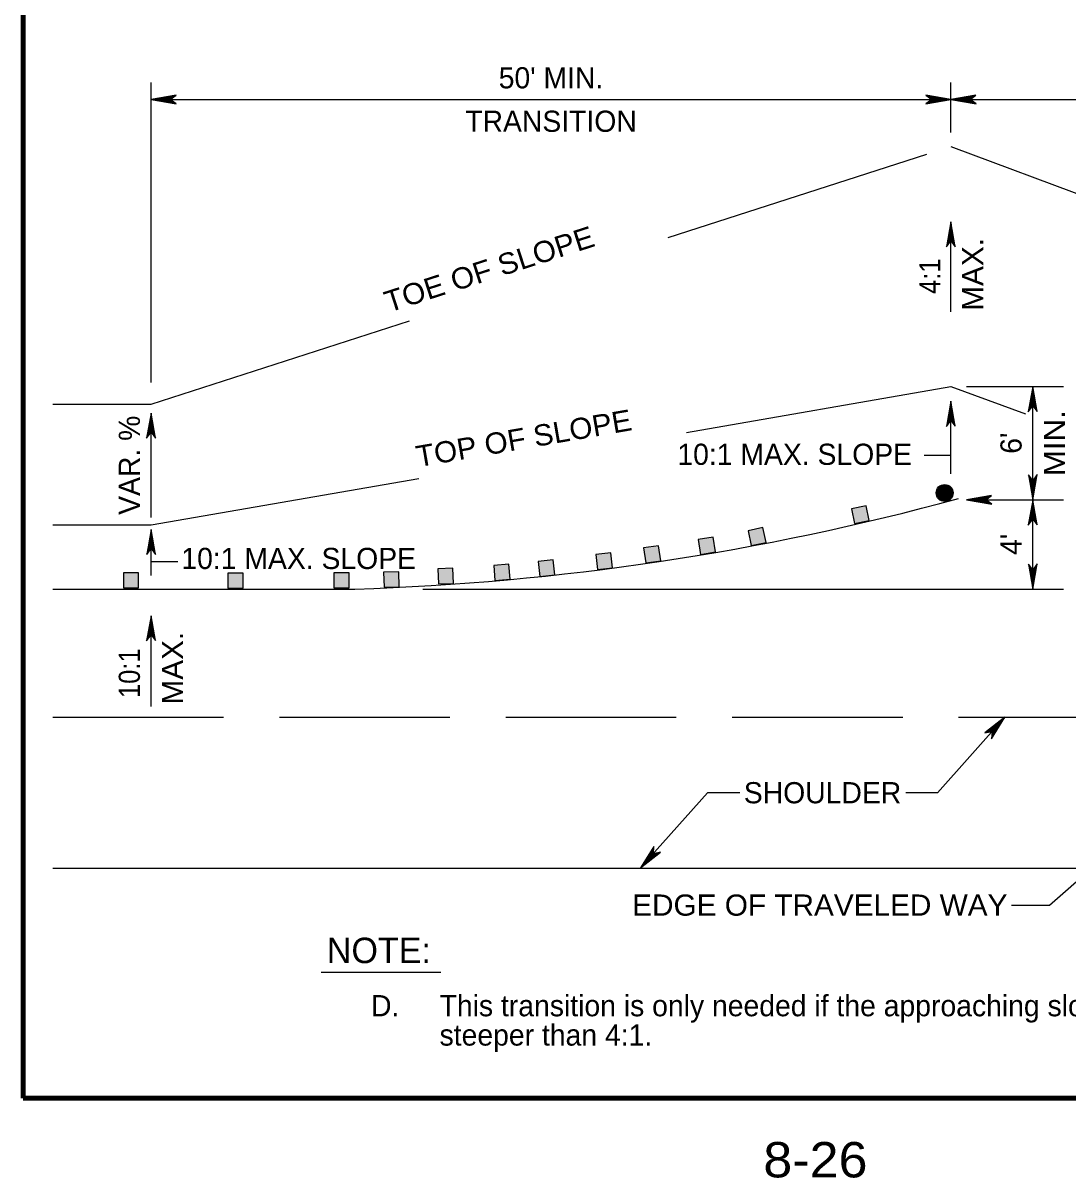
# Model space of a CAD drawing. Extents: x 11.149 to 11.823, y 1.038 to 1.922.
# Drawn here: x 11.1943 to 11.5789, y 1.0551 to 1.4804 of the extents above; entities that cross this region are included whole.
import ezdxf
from ezdxf.enums import TextEntityAlignment as Align

# ---------------------------------------------------------------- set-up
doc = ezdxf.new("R2010")
doc.units = 0
doc.header["$LTSCALE"] = 0.0031
doc.linetypes.add('LONG_DASHED', pattern=[7.5, 6, -1.5])
for name, color, linetype, lineweight in [('1', 7, 'Continuous', 90), ('21', 7, 'Continuous', 25), ('24', 7, 'Continuous', 25), ('5', 7, 'LONG_DASHED', 25), ('60', 7, 'Continuous', 25)]:
    doc.layers.add(name, color=color, linetype=linetype, lineweight=lineweight)

msp = doc.modelspace()

# ---------------------------------------------------------------- hatches: boundary and pattern name
at = {"layer": '60'}
for points in [[(11.499225, 1.301517), (11.500383, 1.296083), (11.505817, 1.297233), (11.504658, 1.302667)], [(11.461208, 1.29345), (11.462367, 1.288017), (11.4678, 1.289175), (11.466642, 1.294608)], [(11.442808, 1.290225), (11.443717, 1.284742), (11.4492, 1.28565), (11.448292, 1.291133)], [(11.405167, 1.2847), (11.4058, 1.279183), (11.411325, 1.279817), (11.410692, 1.285333)], [(11.422742, 1.2871), (11.423517, 1.281592), (11.429017, 1.282367), (11.428242, 1.287867)], [(11.367575, 1.28065), (11.368025, 1.275117), (11.373558, 1.275558), (11.373117, 1.2811)], [(11.383892, 1.282125), (11.384475, 1.2766), (11.39, 1.277175), (11.389417, 1.2827)], [(11.231217, 1.278008), (11.231217, 1.27245), (11.236775, 1.27245), (11.236775, 1.278008)], [(11.269733, 1.277842), (11.269733, 1.272283), (11.275292, 1.272283), (11.275292, 1.277842)], [(11.308758, 1.278008), (11.308758, 1.27245), (11.314317, 1.27245), (11.314317, 1.278008)], [(11.327033, 1.278175), (11.327233, 1.272617), (11.332783, 1.272817), (11.332592, 1.278367)], [(11.346983, 1.279408), (11.347175, 1.273858), (11.352725, 1.27405), (11.352533, 1.279608)]]:
    msp.add_hatch(color=256, dxfattribs=at).paths.add_polyline_path(points)

# ---------------------------------------------------------------- linework, layer by layer
at = {"layer": '1'}
for q in [(11.194317, 1.876217), (11.77765, 1.08455)]:
    msp.add_line((11.194317, 1.08455), q, dxfattribs=at)
at = {"layer": '21'}
for radius in [0.003125, 0.002917, 0.002708, 0.0025, 0.002292, 0.002083, 0.001875, 0.001667, 0.001458, 0.00125, 0.001042, 0.000833, 0.000625, 0.000417, 0.000208]:
    msp.add_circle((11.533558, 1.307351), radius, dxfattribs=at)
at = {"layer": '24'}
for p, q in [((11.241425, 1.348025), (11.241425, 1.458475)), ((11.535867, 1.440125), (11.535867, 1.458475)), ((11.241425, 1.452242), (11.535867, 1.452242)), ((11.535867, 1.452242), (11.599908, 1.452242)), ((11.535867, 1.374), (11.535867, 1.407233)), ((11.541658, 1.346508), (11.577317, 1.346508)), ((11.535867, 1.31445), (11.535867, 1.341108)), ((11.241425, 1.29835), (11.241425, 1.336775)), ((11.53555, 1.321183), (11.525975, 1.321183)), ((11.541658, 1.304875), (11.577317, 1.304875)), ((11.241442, 1.276975), (11.241442, 1.293942)), ((11.251242, 1.28205), (11.241442, 1.28205)), ((11.205308, 1.271983), (11.316425, 1.271983)), ((11.341458, 1.271983), (11.577317, 1.271983)), ((11.241425, 1.228758), (11.241425, 1.262167)), ((11.205308, 1.224767), (11.268108, 1.224767)), ((11.288642, 1.224767), (11.351442, 1.224767)), ((11.371975, 1.224767), (11.434775, 1.224767)), ((11.455308, 1.224767), (11.518108, 1.224767)), ((11.530925, 1.196983), (11.555683, 1.224817)), ((11.538642, 1.224767), (11.601442, 1.224767)), ((11.446283, 1.196983), (11.421642, 1.169275)), ((11.458183, 1.196983), (11.446283, 1.196983)), ((11.530925, 1.196983), (11.519217, 1.196983)), ((11.205308, 1.169208), (11.768167, 1.169208)), ((11.304008, 1.130908), (11.34815, 1.130908))]:
    msp.add_line(p, q, dxfattribs=at)
for points in [[(11.241425, 1.452242), (11.250658, 1.450608), (11.248458, 1.452242), (11.250617, 1.45385), (11.241425, 1.452242), (11.242033, 1.452258), (11.2504, 1.450733), (11.248283, 1.452267), (11.250242, 1.453725), (11.242367, 1.452292), (11.242675, 1.452242), (11.249842, 1.450967), (11.248233, 1.452258), (11.249892, 1.453517), (11.242817, 1.452242), (11.243125, 1.452292), (11.249392, 1.451158), (11.248167, 1.452242), (11.249417, 1.453367), (11.244017, 1.452292), (11.244533, 1.452292), (11.248925, 1.451392), (11.248067, 1.452217), (11.248992, 1.453133), (11.244625, 1.452242), (11.245125, 1.452217), (11.248425, 1.45165), (11.247783, 1.452292), (11.248475, 1.452925), (11.245575, 1.452242), (11.246042, 1.4522), (11.248025, 1.451817), (11.247692, 1.452267), (11.248233, 1.452758), (11.246283, 1.452242), (11.247575, 1.451933), (11.247392, 1.452292), (11.247958, 1.452642), (11.246608, 1.452292), (11.247458, 1.452075), (11.2471, 1.452358), (11.247508, 1.452525), (11.2471, 1.452267), (11.247317, 1.452217)], [(11.535867, 1.452242), (11.526625, 1.453875), (11.528833, 1.452242), (11.526675, 1.450633), (11.535867, 1.452242), (11.53525, 1.452225), (11.526883, 1.453758), (11.529008, 1.452225), (11.52705, 1.450758), (11.534917, 1.4522), (11.534617, 1.452242), (11.527442, 1.453517), (11.52905, 1.452225), (11.5274, 1.450967), (11.534475, 1.452242), (11.534167, 1.4522), (11.5279, 1.453325), (11.529117, 1.452242), (11.527875, 1.451117), (11.533275, 1.4522), (11.53275, 1.4522), (11.528367, 1.453092), (11.529217, 1.452267), (11.5283, 1.45135), (11.532658, 1.452242), (11.532167, 1.452275), (11.528867, 1.452833), (11.5295, 1.452192), (11.528817, 1.451567), (11.531708, 1.452242), (11.53125, 1.452292), (11.529267, 1.452667), (11.529592, 1.452225), (11.52905, 1.451733), (11.531008, 1.452242), (11.529717, 1.45255), (11.5299, 1.4522), (11.529333, 1.451842), (11.530683, 1.452192), (11.529833, 1.452408), (11.530183, 1.452125), (11.529783, 1.451958), (11.530183, 1.452225), (11.529975, 1.452267)], [(11.535867, 1.452242), (11.545108, 1.450608), (11.5429, 1.452242), (11.545058, 1.45385), (11.535867, 1.452242), (11.536483, 1.452258), (11.54485, 1.450733), (11.542725, 1.452267), (11.544683, 1.453725), (11.536808, 1.452292), (11.537117, 1.452242), (11.544283, 1.450967), (11.542675, 1.452258), (11.544333, 1.453517), (11.537258, 1.452242), (11.537567, 1.452292), (11.543833, 1.451158), (11.542617, 1.452242), (11.543858, 1.453367), (11.538458, 1.452292), (11.538983, 1.452292), (11.543367, 1.451392), (11.542517, 1.452217), (11.543433, 1.453133), (11.539075, 1.452242), (11.539567, 1.452217), (11.542867, 1.45165), (11.542233, 1.452292), (11.542917, 1.452925), (11.540017, 1.452242), (11.540483, 1.4522), (11.542467, 1.451817), (11.542142, 1.452267), (11.542683, 1.452758), (11.540725, 1.452242), (11.542017, 1.451933), (11.541833, 1.452292), (11.5424, 1.452642), (11.54105, 1.452292), (11.5419, 1.452075), (11.541542, 1.452358), (11.54195, 1.452525), (11.541542, 1.452267), (11.541758, 1.452217)], [(11.535867, 1.407233), (11.534233, 1.397992), (11.535867, 1.4002), (11.537475, 1.398042), (11.535867, 1.407233), (11.535883, 1.406617), (11.53435, 1.39825), (11.535883, 1.400375), (11.53735, 1.398417), (11.535908, 1.406292), (11.535867, 1.405983), (11.534592, 1.398808), (11.535883, 1.400417), (11.537142, 1.398767), (11.535867, 1.405842), (11.535908, 1.405533), (11.534783, 1.399267), (11.535867, 1.400483), (11.536992, 1.399242), (11.535908, 1.404642), (11.535908, 1.404117), (11.535017, 1.399733), (11.535842, 1.400583), (11.536758, 1.399667), (11.535867, 1.404025), (11.535833, 1.403533), (11.535275, 1.400233), (11.535917, 1.400867), (11.536542, 1.400183), (11.535867, 1.403075), (11.535817, 1.402617), (11.535442, 1.400633), (11.535883, 1.400958), (11.536375, 1.400417), (11.535867, 1.402375), (11.535558, 1.401083), (11.535908, 1.401267), (11.536267, 1.4007), (11.535917, 1.40205), (11.5357, 1.4012), (11.535983, 1.401558), (11.53615, 1.40115), (11.535883, 1.40155), (11.535842, 1.401342)], [(11.565983, 1.346508), (11.56435, 1.337267), (11.565983, 1.339475), (11.567592, 1.337317), (11.565983, 1.346508), (11.566, 1.345892), (11.564475, 1.337525), (11.566008, 1.33965), (11.567467, 1.337692), (11.566033, 1.345558), (11.565983, 1.34525), (11.564708, 1.338083), (11.566008, 1.339692), (11.567258, 1.338042), (11.565983, 1.345117), (11.566033, 1.344808), (11.5649, 1.338542), (11.565983, 1.339758), (11.567117, 1.338517), (11.566033, 1.343917), (11.566033, 1.343392), (11.565133, 1.339008), (11.565958, 1.339858), (11.566875, 1.338942), (11.565983, 1.3433), (11.565958, 1.342808), (11.565392, 1.339508), (11.566033, 1.340142), (11.566667, 1.339458), (11.565983, 1.34235), (11.565942, 1.341883), (11.565558, 1.339908), (11.566008, 1.340233), (11.5665, 1.339692), (11.565983, 1.34165), (11.565675, 1.340358), (11.566033, 1.340542), (11.566383, 1.339975), (11.566033, 1.341325), (11.565817, 1.340475), (11.5661, 1.340825), (11.566267, 1.340425), (11.566008, 1.340825), (11.565958, 1.340617)], [(11.565983, 1.271983), (11.565983, 1.304875), (11.565983, 1.346508)], [(11.535867, 1.341108), (11.534233, 1.331867), (11.535867, 1.334075), (11.537475, 1.331917), (11.535867, 1.341108), (11.535883, 1.340492), (11.53435, 1.332125), (11.535883, 1.334242), (11.53735, 1.332283), (11.535908, 1.340158), (11.535867, 1.33985), (11.534592, 1.332683), (11.535883, 1.334292), (11.537142, 1.332642), (11.535867, 1.339708), (11.535908, 1.339408), (11.534783, 1.333142), (11.535867, 1.334358), (11.536992, 1.333117), (11.535908, 1.338517), (11.535908, 1.337992), (11.535017, 1.333608), (11.535842, 1.334458), (11.536758, 1.333542), (11.535867, 1.3379), (11.535833, 1.337408), (11.535275, 1.334108), (11.535917, 1.334742), (11.536542, 1.33405), (11.535867, 1.33695), (11.535817, 1.336483), (11.535442, 1.334508), (11.535883, 1.334833), (11.536375, 1.334292), (11.535867, 1.336242), (11.535558, 1.33495), (11.535908, 1.335142), (11.536267, 1.334575), (11.535917, 1.335917), (11.5357, 1.335075), (11.535983, 1.335425), (11.53615, 1.335017), (11.535883, 1.335425), (11.535842, 1.335217)], [(11.535867, 1.341108), (11.534233, 1.331867), (11.535867, 1.334075), (11.537475, 1.331917), (11.535867, 1.341108), (11.535883, 1.340492), (11.53435, 1.332125), (11.535883, 1.334242), (11.53735, 1.332283), (11.535908, 1.340158), (11.535867, 1.33985), (11.534592, 1.332683), (11.535883, 1.334292), (11.537142, 1.332642), (11.535867, 1.339708), (11.535908, 1.339408), (11.534783, 1.333142), (11.535867, 1.334358), (11.536992, 1.333117), (11.535908, 1.338517), (11.535908, 1.337992), (11.535017, 1.333608), (11.535842, 1.334458), (11.536758, 1.333542), (11.535867, 1.3379), (11.535833, 1.337408), (11.535275, 1.334108), (11.535917, 1.334742), (11.536542, 1.33405), (11.535867, 1.33695), (11.535817, 1.336483), (11.535442, 1.334508), (11.535883, 1.334833), (11.536375, 1.334292), (11.535867, 1.336242), (11.535558, 1.33495), (11.535908, 1.335142), (11.536267, 1.334575), (11.535917, 1.335917), (11.5357, 1.335075), (11.535983, 1.335425), (11.53615, 1.335017), (11.535883, 1.335425), (11.535842, 1.335217)], [(11.241425, 1.336775), (11.239792, 1.327533), (11.241425, 1.329742), (11.243033, 1.327583), (11.241425, 1.336775), (11.241442, 1.336167), (11.239908, 1.3278), (11.241442, 1.329917), (11.2429, 1.327958), (11.241467, 1.335833), (11.241425, 1.335525), (11.24015, 1.328358), (11.241442, 1.329967), (11.242692, 1.328308), (11.241425, 1.335383), (11.241467, 1.335075), (11.240333, 1.328808), (11.241425, 1.330033), (11.24255, 1.328783), (11.241467, 1.334183), (11.241467, 1.333667), (11.240567, 1.329275), (11.241392, 1.330133), (11.242317, 1.329208), (11.241425, 1.333567), (11.241392, 1.333075), (11.240825, 1.329775), (11.241467, 1.330408), (11.2421, 1.329725), (11.241425, 1.332625), (11.241375, 1.332158), (11.241, 1.330175), (11.241442, 1.3305), (11.241933, 1.329967), (11.241417, 1.331917), (11.241117, 1.330625), (11.241467, 1.330808), (11.241825, 1.330242), (11.241467, 1.331592), (11.241258, 1.330742), (11.241533, 1.3311), (11.2417, 1.330692), (11.241442, 1.3311), (11.241392, 1.330883)], [(11.565983, 1.304875), (11.567617, 1.314117), (11.565983, 1.311908), (11.564375, 1.314067), (11.565983, 1.304875), (11.565967, 1.305492), (11.5675, 1.313858), (11.565967, 1.311742), (11.564508, 1.3137), (11.565942, 1.305825), (11.565983, 1.306133), (11.567258, 1.3133), (11.565967, 1.311692), (11.564717, 1.313342), (11.565983, 1.306275), (11.565942, 1.306575), (11.567075, 1.312842), (11.565983, 1.311625), (11.564858, 1.312867), (11.565942, 1.307467), (11.565942, 1.307992), (11.566842, 1.312375), (11.566008, 1.311525), (11.565092, 1.312442), (11.565983, 1.308083), (11.566017, 1.308575), (11.566583, 1.311875), (11.565942, 1.311242), (11.565308, 1.311933), (11.565983, 1.309033), (11.566033, 1.3095), (11.566408, 1.311475), (11.565967, 1.31115), (11.565475, 1.311692), (11.565983, 1.309742), (11.566292, 1.311033), (11.565942, 1.310842), (11.565583, 1.311408), (11.565942, 1.310067), (11.56615, 1.310908), (11.565875, 1.310558), (11.565708, 1.310967), (11.565967, 1.310558), (11.566008, 1.310767)], [(11.541658, 1.304875), (11.5509, 1.303242), (11.548692, 1.304875), (11.55085, 1.306483), (11.541658, 1.304875), (11.542267, 1.304892), (11.550633, 1.303367), (11.548517, 1.3049), (11.550475, 1.306358), (11.5426, 1.304925), (11.542908, 1.304875), (11.550075, 1.3036), (11.548467, 1.3049), (11.550125, 1.30615), (11.54305, 1.304875), (11.543358, 1.304925), (11.549625, 1.303792), (11.5484, 1.304875), (11.54965, 1.306008), (11.54425, 1.304925), (11.544767, 1.304925), (11.549158, 1.304025), (11.5483, 1.30485), (11.549225, 1.305767), (11.544867, 1.304875), (11.545358, 1.30485), (11.548658, 1.304283), (11.548025, 1.304925), (11.548708, 1.305558), (11.545808, 1.304875), (11.546275, 1.304833), (11.548258, 1.30445), (11.547933, 1.3049), (11.548467, 1.305392), (11.546517, 1.304875), (11.547808, 1.304567), (11.547625, 1.304925), (11.548192, 1.305275), (11.546842, 1.304925), (11.547692, 1.304708), (11.547333, 1.304992), (11.547742, 1.305158), (11.547333, 1.3049), (11.54755, 1.30485)], [(11.565983, 1.304767), (11.56435, 1.295525), (11.565983, 1.297733), (11.567592, 1.295575), (11.565983, 1.304767), (11.566, 1.30415), (11.564475, 1.295783), (11.566008, 1.2979), (11.567467, 1.295942), (11.566033, 1.303817), (11.565983, 1.303508), (11.564708, 1.296342), (11.566008, 1.29795), (11.567258, 1.2963), (11.565983, 1.303367), (11.566033, 1.303067), (11.5649, 1.2968), (11.565983, 1.298017), (11.567117, 1.296775), (11.566033, 1.302167), (11.566033, 1.30165), (11.565133, 1.297258), (11.565958, 1.298117), (11.566875, 1.2972), (11.565983, 1.301558), (11.565958, 1.301067), (11.565392, 1.297767), (11.566033, 1.2984), (11.566667, 1.297708), (11.565983, 1.300608), (11.565942, 1.300142), (11.565558, 1.298167), (11.566008, 1.298492), (11.5665, 1.29795), (11.565983, 1.2999), (11.565675, 1.298608), (11.566033, 1.2988), (11.566383, 1.298233), (11.566033, 1.299575), (11.565817, 1.298733), (11.5661, 1.299083), (11.566267, 1.298675), (11.566008, 1.299083), (11.565958, 1.298867)], [(11.241442, 1.293942), (11.239808, 1.2847), (11.241442, 1.286908), (11.24305, 1.284742), (11.241442, 1.293942), (11.241458, 1.293325), (11.239925, 1.284958), (11.241458, 1.287075), (11.242917, 1.285117), (11.241483, 1.292992), (11.241442, 1.292683), (11.240167, 1.285517), (11.241458, 1.287125), (11.242708, 1.285475), (11.241442, 1.292542), (11.241483, 1.292242), (11.24035, 1.285975), (11.241442, 1.287192), (11.242567, 1.28595), (11.241483, 1.291342), (11.241483, 1.290825), (11.240583, 1.286433), (11.241408, 1.287292), (11.242333, 1.286375), (11.241442, 1.290733), (11.241408, 1.290233), (11.240842, 1.286942), (11.241483, 1.287575), (11.242117, 1.286883), (11.241442, 1.289783), (11.241392, 1.289317), (11.241017, 1.287342), (11.241458, 1.287667), (11.24195, 1.287125), (11.241433, 1.289075), (11.241133, 1.287783), (11.241483, 1.287975), (11.241842, 1.287408), (11.241483, 1.28875), (11.241275, 1.287908), (11.24155, 1.288258), (11.241717, 1.28785), (11.241458, 1.288258), (11.241408, 1.288042)], [(11.565983, 1.271983), (11.567617, 1.281225), (11.565983, 1.279017), (11.564375, 1.281183), (11.565983, 1.271983), (11.565967, 1.2726), (11.5675, 1.280967), (11.565967, 1.27885), (11.564508, 1.280808), (11.565942, 1.272933), (11.565983, 1.273242), (11.567258, 1.280408), (11.565967, 1.2788), (11.564717, 1.28045), (11.565983, 1.273383), (11.565942, 1.273683), (11.567075, 1.27995), (11.565983, 1.278733), (11.564858, 1.279975), (11.565942, 1.274583), (11.565942, 1.2751), (11.566842, 1.279492), (11.566008, 1.278633), (11.565092, 1.27955), (11.565983, 1.275192), (11.566017, 1.275692), (11.566583, 1.278983), (11.565942, 1.27835), (11.565308, 1.279042), (11.565983, 1.276142), (11.566033, 1.276608), (11.566408, 1.278583), (11.565967, 1.278258), (11.565475, 1.2788), (11.565983, 1.27685), (11.566292, 1.278142), (11.565942, 1.27795), (11.565583, 1.278517), (11.565942, 1.277175), (11.56615, 1.278017), (11.565875, 1.277667), (11.565708, 1.278075), (11.565967, 1.277667), (11.566008, 1.277883)], [(11.241425, 1.262167), (11.239792, 1.252925), (11.241425, 1.255133), (11.243033, 1.252975), (11.241425, 1.262167), (11.241442, 1.26155), (11.239908, 1.253183), (11.241442, 1.255308), (11.2429, 1.25335), (11.241467, 1.261225), (11.241425, 1.260917), (11.24015, 1.25375), (11.241442, 1.255358), (11.242692, 1.2537), (11.241425, 1.260775), (11.241467, 1.260467), (11.240333, 1.2542), (11.241425, 1.255417), (11.24255, 1.254175), (11.241467, 1.259575), (11.241467, 1.25905), (11.240567, 1.254667), (11.241392, 1.255517), (11.242317, 1.2546), (11.241425, 1.258958), (11.241392, 1.258467), (11.240825, 1.255167), (11.241467, 1.2558), (11.2421, 1.255117), (11.241425, 1.258017), (11.241375, 1.25755), (11.241, 1.255567), (11.241442, 1.255892), (11.241933, 1.25535), (11.241417, 1.257308), (11.241117, 1.256017), (11.241467, 1.2562), (11.241825, 1.255633), (11.241467, 1.256983), (11.241258, 1.256133), (11.241533, 1.256492), (11.2417, 1.256083), (11.241442, 1.256483), (11.241392, 1.256275)], [(11.555683, 1.224817), (11.548317, 1.219), (11.551008, 1.219567), (11.550775, 1.216883), (11.555683, 1.224817), (11.555283, 1.22435), (11.548583, 1.219117), (11.551133, 1.219683), (11.550925, 1.217242), (11.555083, 1.224083), (11.55485, 1.223883), (11.549133, 1.219375), (11.551167, 1.219717), (11.551008, 1.21765), (11.55475, 1.223783), (11.554583, 1.223517), (11.549575, 1.219592), (11.5512, 1.219775), (11.551208, 1.2181), (11.553992, 1.22285), (11.553642, 1.222467), (11.550058, 1.219783), (11.551242, 1.219867), (11.551317, 1.218575), (11.55355, 1.222425), (11.5532, 1.222075), (11.550583, 1.219983), (11.551483, 1.220033), (11.5515, 1.2191), (11.552917, 1.221717), (11.552575, 1.2214), (11.550975, 1.220167), (11.551525, 1.220117), (11.551533, 1.219383), (11.55245, 1.221192), (11.551358, 1.220425), (11.55175, 1.220333), (11.551642, 1.219675), (11.552267, 1.220917), (11.55155, 1.220425), (11.551992, 1.2205), (11.551842, 1.220083), (11.551917, 1.220558), (11.551742, 1.220433)], [(11.421642, 1.169275), (11.429008, 1.1751), (11.426317, 1.174533), (11.42655, 1.177217), (11.421642, 1.169275), (11.422042, 1.16975), (11.428742, 1.174983), (11.426192, 1.174417), (11.4264, 1.17685), (11.422242, 1.170017), (11.422475, 1.170217), (11.428192, 1.174725), (11.426158, 1.174383), (11.426317, 1.17645), (11.422575, 1.170317), (11.422742, 1.170575), (11.42775, 1.174508), (11.426133, 1.174317), (11.426117, 1.176), (11.423333, 1.171242), (11.423683, 1.171633), (11.427267, 1.174317), (11.426083, 1.174225), (11.426008, 1.175525), (11.423775, 1.171675), (11.424125, 1.172025), (11.426742, 1.174117), (11.425842, 1.174067), (11.425825, 1.175), (11.424408, 1.172383), (11.42475, 1.1727), (11.42635, 1.173925), (11.4258, 1.173975), (11.425792, 1.174708), (11.424875, 1.172908), (11.425967, 1.173667), (11.425575, 1.173767), (11.425692, 1.174425), (11.425058, 1.173183), (11.425775, 1.173675), (11.425333, 1.1736), (11.425483, 1.174008), (11.425408, 1.173533), (11.425583, 1.173667)], [(11.558225, 1.1556), (11.572117, 1.1556), (11.588, 1.16945)]]:
    msp.add_lwpolyline(points, dxfattribs=at)
msp.add_arc((11.286375, 2.229705), 0.958189, 271.79696, 285.26457, dxfattribs=at)
at = {"layer": '5'}
for p, q in [((11.241425, 1.340042), (11.535867, 1.434983)), ((11.535867, 1.434983), (11.674758, 1.3831)), ((11.241425, 1.2956), (11.535867, 1.346508)), ((11.535867, 1.346508), (11.563308, 1.33645)), ((11.205308, 1.340042), (11.241425, 1.340042)), ((11.205308, 1.2956), (11.241425, 1.2956))]:
    msp.add_line(p, q, dxfattribs=at)
at = {"layer": '60'}
for points in [[(11.499225, 1.301517), (11.500383, 1.296083), (11.505817, 1.297233), (11.504658, 1.302667)], [(11.461208, 1.29345), (11.462367, 1.288017), (11.4678, 1.289175), (11.466642, 1.294608)], [(11.442808, 1.290225), (11.443717, 1.284742), (11.4492, 1.28565), (11.448292, 1.291133)], [(11.405167, 1.2847), (11.4058, 1.279183), (11.411325, 1.279817), (11.410692, 1.285333)], [(11.422742, 1.2871), (11.423517, 1.281592), (11.429017, 1.282367), (11.428242, 1.287867)], [(11.367575, 1.28065), (11.368025, 1.275117), (11.373558, 1.275558), (11.373117, 1.2811)], [(11.383892, 1.282125), (11.384475, 1.2766), (11.39, 1.277175), (11.389417, 1.2827)], [(11.231217, 1.278008), (11.231217, 1.27245), (11.236775, 1.27245), (11.236775, 1.278008)], [(11.269733, 1.277842), (11.269733, 1.272283), (11.275292, 1.272283), (11.275292, 1.277842)], [(11.308758, 1.278008), (11.308758, 1.27245), (11.314317, 1.27245), (11.314317, 1.278008)], [(11.327033, 1.278175), (11.327233, 1.272617), (11.332783, 1.272817), (11.332592, 1.278367)], [(11.346983, 1.279408), (11.347175, 1.273858), (11.352725, 1.27405), (11.352533, 1.279608)]]:
    msp.add_lwpolyline(points, close=True, dxfattribs=at)

# ---------------------------------------------------------------- texts
at = {"layer": '1'}
for s, height, p in [("50' MIN.", 0.0078, (11.38865, 1.456342)), ('TRANSITION', 0.0078, (11.388654, 1.440342)), ('10:1 MAX. SLOPE', 0.0078, (11.478358, 1.317708)), ('10:1 MAX. SLOPE', 0.0078, (11.295767, 1.27935)), ('SHOULDER', 0.0078, (11.488604, 1.193083)), ('NOTE:', 0.009375, (11.325292, 1.134225)), ('D.', 0.0078, (11.327621, 1.114658))]:
    msp.add_text(s, height=height, dxfattribs=at).set_placement(p, align=Align.CENTER)
for s, rotation, width, p in [('TOE OF SLOPE', 17.871, 1.05, (11.367107, 1.386053)), ('MAX.', 90, 1.05, (11.547767, 1.387854)), ('4:1', 90, 0.9, (11.531992, 1.387175)), ('TOP OF SLOPE', 9.809, 1.05, (11.379286, 1.323689)), ('MIN.', 90, 1.1, (11.577883, 1.325692)), ('MAX.', 90, 1.05, (11.253233, 1.242846)), ('10:1', 90, 0.9, (11.237325, 1.240988))]:
    msp.add_text(s, height=0.0078, rotation=rotation, dxfattribs=dict(at, width=width)).set_placement(p, align=Align.CENTER)
for s, p in [('VAR. %', (11.237325, 1.317562)), ("6'", (11.561883, 1.325692)), ("4'", (11.561883, 1.288433))]:
    msp.add_text(s, height=0.0078, rotation=90, dxfattribs=at).set_placement(p, align=Align.CENTER)
for s, height, width, p in [('EDGE OF TRAVELED WAY', 0.0078, 1.05, (11.487604, 1.1517)), ('8-26', 0.01303, 1.1, (11.485979, 1.055325))]:
    msp.add_text(s, height=height, dxfattribs=dict(at, width=width)).set_placement(p, align=Align.CENTER)
for s, p in [('This transition is only needed if the approaching slope is', (11.347625, 1.114658)), ('steeper than 4:1.', (11.347625, 1.103858))]:
    msp.add_text(s, height=0.0078, dxfattribs=at).set_placement(p)

doc.saveas('drawing.dxf')
